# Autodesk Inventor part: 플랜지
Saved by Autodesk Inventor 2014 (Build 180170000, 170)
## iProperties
Created: 2026-04
Part Number: 플랜지
Material: 일반
Document SubType Name: Modeling
Designer: dg
Density: 1 g/cm^3
Appearance: 기본값
Author: dg
Author: jhkim
Creation Date: 2026-03-26
Sending System: Autodesk Inventor 2026
Preprocessor: ST-DEVELOPER v20.1
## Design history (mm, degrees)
node "플랜지1"
node "솔리드1"
node "기준1"
